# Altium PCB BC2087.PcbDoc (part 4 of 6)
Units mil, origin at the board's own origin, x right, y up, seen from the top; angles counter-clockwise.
Board outline 7401.57 x 1181.1 mil, 6 copper layers (Top Copper, Signal Layer 1, Signal Layer 2, Signal Layer 3, Signal Layer 4, Bottom Copper), stack 62.874 mil thick; 302 components, 237 nets, 1184 pads, 867 vias.
Unrouted connection lines stored in the file: 315.
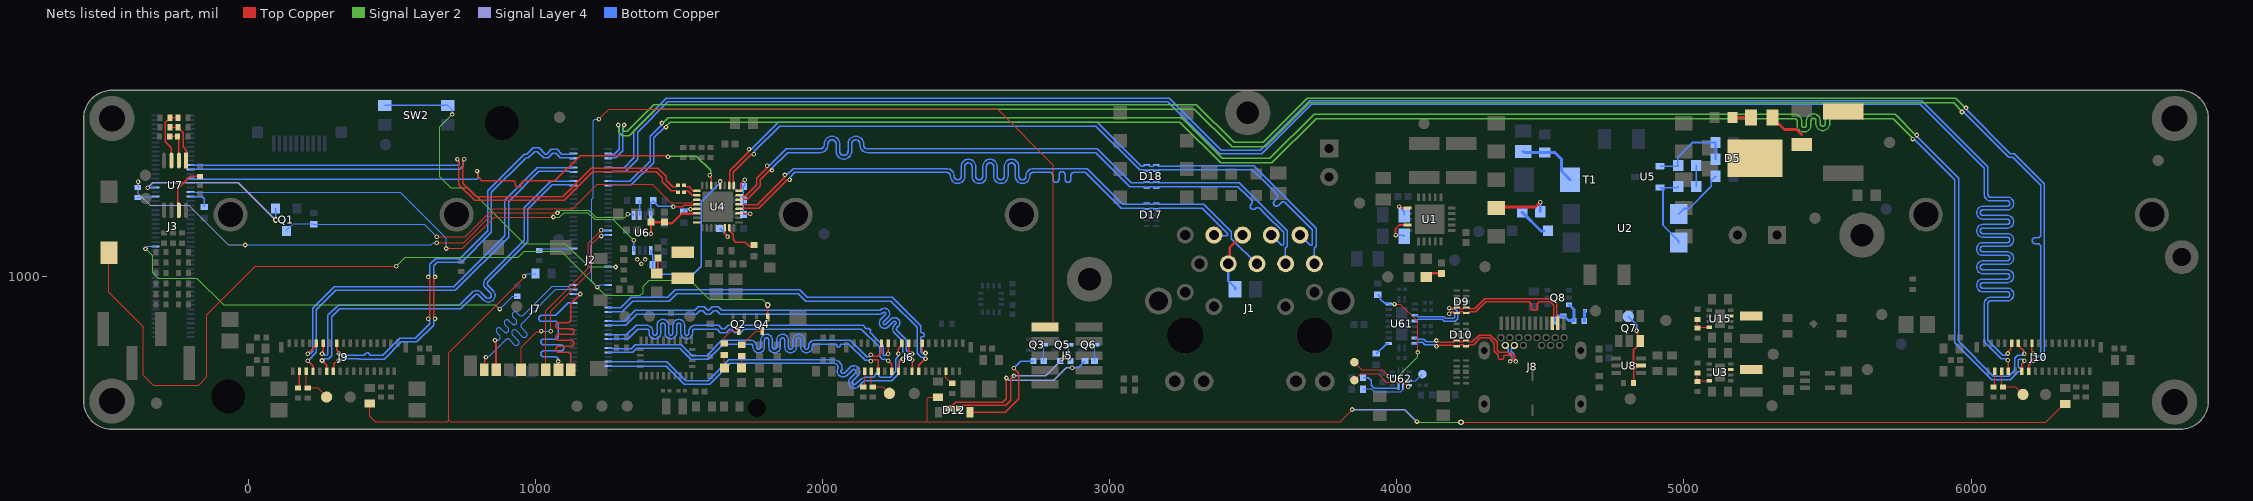
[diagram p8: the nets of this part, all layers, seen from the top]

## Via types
v1: diameter 20, hole 10, Top Copper to Bottom Copper, 273 vias
v2: diameter 16, hole 8, Top Copper to Bottom Copper, tented both sides, 243 vias
v3: diameter 15.98, hole 7.99, Top Copper to Bottom Copper, tented both sides, 201 vias
v4: diameter 18, hole 8, Top Copper to Bottom Copper, tented both sides, 70 vias
v5: diameter 16, hole 7.95, Top Copper to Bottom Copper, tented both sides, 36 vias
v6: diameter 20, hole 10, Top Copper to Bottom Copper, tented both sides, 26 vias
v7: diameter 16, hole 8, Top Copper to Bottom Copper, 17 vias
v8: diameter 19.68, hole 11.81, Top Copper to Bottom Copper, tented both sides, 1 vias

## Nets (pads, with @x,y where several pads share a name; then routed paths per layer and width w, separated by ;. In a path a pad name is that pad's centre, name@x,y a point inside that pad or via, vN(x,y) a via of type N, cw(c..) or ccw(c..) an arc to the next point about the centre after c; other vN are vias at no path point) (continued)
MD2_N: D17.5 D17.6 J1.6 U4.5 | length 2394.4
  Top Copper w5.12: U4.5@1708.96,1252.91 1719.55,1252.91 1721.03,1251.44 1771.68,1251.44 1867.87,1347.63 v3(1867.87,1355.2)
  Bottom Copper w5.12: v3(1867.87,1355.2) 1875.45,1355.2 1897.21,1376.96 2358.89,1376.96 2432.43,1376.96 cw(c2432.43,1351.77) 2457.62,1351.77 2457.62,1350.87 ccw(c2470.02,1350.87) 2470.02,1338.47 ccw(c2470.02,1350.87) 2482.42,1350.87 2482.42,1384.85 cw(c2507.61,1384.85) 2507.61,1410.04 cw(c2507.61,1384.85) 2532.8,1384.85 2532.8,1350.87 ccw(c2545.2,1350.87) 2545.2,1338.47 ccw(c2545.2,1350.87) 2557.61,1350.87 2557.61,1384.85 cw(c2582.8,1384.85) 2582.8,1410.04 cw(c2582.8,1384.85) 2607.99,1384.85 2607.99,1350.87 ccw(c2620.39,1350.87) 2620.39,1338.47 ccw(c2620.39,1350.87) 2632.79,1350.87 2632.79,1384.85 cw(c2657.98,1384.85) 2657.98,1410.04 cw(c2657.98,1384.85) 2683.18,1384.85 2683.18,1350.87 ccw(c2695.58,1350.87) 2695.58,1338.47 ccw(c2695.58,1350.87) 2707.98,1350.87 2707.98,1351.77 cw(c2733.17,1351.77) 2733.17,1376.96 2742.13,1376.96 2920.65,1376.96 3045.16,1252.46 3117.91,1252.46 3121.36,1255.91 D17.5@3128.54,1255.91 3135.73,1255.91 3139.18,1252.46 3150.78,1252.46 3154.23,1255.91 D17.6@3161.42,1255.91 3168.6,1255.91 3172.05,1252.46 3327.88,1252.46 3423.87,1156.47 3423.87,1133.42 3511.56,1045.73 J1.6@3512.6,1045.73
MD2_P: D17.4 D17.7 J1.3 U4.4 | length 2394.5
  Top Copper w5.12: U4.4@1708.96,1237.17 1719.55,1237.17 1721.03,1238.65 1776.98,1238.65 1876.92,1338.58 v3(1884.49,1338.58)
  Bottom Copper w5.12: v3(1884.49,1338.58) 1884.49,1346.16 1902.51,1364.17 2358.89,1364.17 2432.43,1364.17 cw(c2432.43,1351.77) 2444.83,1351.77 2444.83,1350.87 ccw(c2470.02,1350.87) 2470.02,1325.68 ccw(c2470.02,1350.87) 2495.21,1350.87 2495.21,1384.85 cw(c2507.61,1384.85) 2507.61,1397.25 cw(c2507.61,1384.85) 2520.01,1384.85 2520.01,1350.87 ccw(c2545.2,1350.87) 2545.2,1325.68 ccw(c2545.2,1350.87) 2570.4,1350.87 2570.4,1384.85 cw(c2582.8,1384.85) 2582.8,1397.25 cw(c2582.8,1384.85) 2595.2,1384.85 2595.2,1350.87 ccw(c2620.39,1350.87) 2620.39,1325.68 ccw(c2620.39,1350.87) 2645.58,1350.87 2645.58,1384.85 cw(c2657.98,1384.85) 2657.98,1397.25 cw(c2657.98,1384.85) 2670.39,1384.85 2670.39,1350.87 ccw(c2695.58,1350.87) 2695.58,1325.68 ccw(c2695.58,1350.87) 2720.77,1350.87 2720.77,1351.77 cw(c2733.17,1351.77) 2733.17,1364.17 2742.13,1364.17 2768.41,1364.17 2791.83,1364.17 cw(c2791.83,1353.74) 2802.26,1353.74 2802.26,1339.64 ccw(c2812.7,1339.64) 2812.7,1329.2 ccw(c2812.7,1339.64) 2823.13,1339.64 2823.13,1356.41 cw(c2833.56,1356.41) 2833.56,1366.85 cw(c2833.56,1356.41) 2844,1356.41 2844,1339.64 ccw(c2854.43,1339.64) 2854.43,1329.2 ccw(c2854.43,1339.64) 2864.86,1339.64 2864.86,1353.74 cw(c2875.3,1353.74) 2875.3,1364.17 2894.1,1364.17 2915.35,1364.17 3039.86,1239.67 3117.91,1239.67 3121.36,1236.22 D17.4@3128.54,1236.22 3135.73,1236.22 3139.18,1239.67 3150.78,1239.67 3154.23,1236.22 D17.7@3161.42,1236.22 3168.6,1236.22 3172.05,1239.67 3322.58,1239.67 3411.08,1151.17 3411.08,1146.93 3408.08,1143.93 3364.4,1143.93 J1.3@3362.6,1145.73
MD3_N: D18.2 D18.9 J1.8 U4.7 | length 2389.1
  Top Copper w5.12: U4.7@1708.96,1284.41 1719.55,1284.41 1721.03,1282.93 1732.17,1282.93 1770.14,1320.9 1770.14,1343.69 1806.52,1380.07 v3(1806.52,1387.64)
  Bottom Copper w5.12: v3(1806.52,1387.64) 1814.09,1387.64 1872.31,1445.86 1927.17,1445.86 1990.71,1445.86 ccw(c1990.71,1460.23) 2005.08,1460.23 2005.08,1463.14 cw(c2032.24,1463.14) 2032.24,1490.3 cw(c2032.24,1463.14) 2059.4,1463.14 2059.4,1437.55 ccw(c2073.77,1437.55) 2073.77,1423.18 ccw(c2073.77,1437.55) 2088.14,1437.55 2088.14,1463.14 cw(c2115.3,1463.14) 2115.3,1490.3 cw(c2115.3,1463.14) 2142.46,1463.14 2142.46,1460.23 ccw(c2156.83,1460.23) 2156.83,1445.86 2207.32,1445.86 2955.71,1445.86 3074.31,1327.26 3117.91,1327.26 3121.36,1330.71 D18.2@3128.54,1330.71 3135.73,1330.71 3139.18,1327.26 3150.78,1327.26 3154.23,1330.71 D18.9@3161.42,1330.71 3164.67,1330.71 3168.11,1327.26 3451.77,1327.26 3618.66,1160.37 3618.66,1107.4 3611.92,1100.65 3611.92,1046.41 J1.8@3612.6,1045.73
MD3_P: D18.1 D18.10 J1.7 U4.6 | length 2395.7
  Top Copper w5.12: U4.6@1708.96,1268.66 1719.55,1268.66 1721.03,1270.14 1737.47,1270.14 1782.93,1315.6 1782.93,1338.39 1815.56,1371.02 v3(1823.13,1371.02)
  Bottom Copper w5.12: v3(1823.13,1371.02) 1823.13,1378.6 1877.61,1433.07 1927.17,1433.07 1990.71,1433.07 ccw(c1990.71,1460.23) 2017.87,1460.23 2017.87,1463.14 cw(c2032.24,1463.14) 2032.24,1477.51 cw(c2032.24,1463.14) 2046.61,1463.14 2046.61,1437.55 ccw(c2073.77,1437.55) 2073.77,1410.38 ccw(c2073.77,1437.55) 2100.93,1437.55 2100.93,1463.14 cw(c2115.3,1463.14) 2115.3,1477.51 cw(c2115.3,1463.14) 2129.67,1463.14 2129.67,1460.23 ccw(c2156.83,1460.23) 2156.83,1433.07 2207.32,1433.07 2950.42,1433.07 3069.02,1314.47 3117.91,1314.47 3121.36,1311.02 D18.1@3128.54,1311.02 3135.73,1311.02 3139.18,1314.47 3150.78,1314.47 3154.23,1311.02 D18.10@3161.42,1311.02 3164.67,1311.02 3168.11,1314.47 3446.47,1314.47 3476.35,1284.59 3478.16,1282.78 3492.92,1268.03 cw(c3485.54,1260.65) 3492.92,1253.28 3492.7,1253.06 ccw(c3500.08,1245.68) 3492.7,1238.3 ccw(c3500.08,1245.68) 3507.45,1238.3 3507.67,1238.52 cw(c3515.05,1231.14) 3522.42,1238.52 3540.08,1220.86 3541.89,1219.05 3605.87,1155.07 3605.87,1112.69 3602.87,1109.7 3598.63,1109.7 J1.7@3562.6,1145.73 J1.7@3576.55,1145.73
MD4_N: D18.5 D18.6 J1.10 U4.10 | length 2453.9
  Top Copper w5.12: U4.10@1674.51,1318.86 1674.51,1329.45 1675.99,1330.93 1675.99,1369.15 1740.68,1433.84 1740.68,1441.41 v3(1743.52,1444.26)
  Bottom Copper w5.12: v3(1743.52,1444.26) 1745.6,1446.33 1753.18,1446.33 1845.22,1538.38 2956.74,1538.38 3108.81,1386.32 3117.91,1386.32 3121.36,1389.76 D18.5@3128.54,1389.76 3135.73,1389.76 3139.18,1386.32 3150.78,1386.32 3154.23,1389.76 D18.6@3161.42,1389.76 3164.67,1389.76 3168.11,1386.32 3242.07,1386.32 3242.56,1386.81 3501.36,1386.81 3718.66,1169.5 3718.66,1107.4 3711.92,1100.65 3711.92,1046.41 J1.10@3712.6,1045.73
MD4_P: D18.4 D18.7 J1.9 U4.9 | length 2449.8
  Top Copper w5.12: U4.9@1690.26,1318.86 1690.26,1329.45 1688.78,1330.93 1688.78,1363.85 1749.72,1424.79 1757.29,1424.79 v3(1760.14,1427.64)
  Bottom Copper w5.12: v3(1760.14,1427.64) 1762.22,1429.72 1762.22,1437.29 1850.52,1525.59 2951.45,1525.59 3103.51,1373.53 3117.91,1373.53 3121.36,1370.08 D18.4@3128.54,1370.08 3135.73,1370.08 3139.18,1373.53 3150.78,1373.53 3154.23,1370.08 D18.7@3161.42,1370.08 3164.67,1370.08 3168.11,1373.53 3247.37,1373.53 3247.86,1374.02 3496.06,1374.02 3565.45,1304.63 3567.26,1302.82 3582.02,1288.06 cw(c3574.64,1280.68) 3582.02,1273.31 3573.13,1264.42 ccw(c3580.51,1257.05) 3573.13,1249.67 ccw(c3580.51,1257.05) 3587.89,1249.67 3596.77,1258.55 cw(c3604.15,1251.18) 3611.53,1258.55 3640.61,1229.47 3642.42,1227.66 3705.87,1164.21 3705.87,1112.69 3702.87,1109.7 3698.63,1109.7 J1.9@3662.6,1145.73
MIPI_RX2_C_N: J2.95 J10.20 | length 6095.5
  Top Copper w5.12: J10.20@6200.93,671.88 6200.93,691.9 v2(6217.39,708.36)
  Signal Layer 2 w5.12: v5(1308,1529.07) 1305.4,1526.47 1305.4,1510.87 1308.4,1507.87 1318.9,1507.87 1411.31,1600.28 3301.29,1600.28 3432.94,1468.64 3534.64,1468.64 3687.94,1621.94 5946.39,1621.94 5979.62,1588.71 v2(5982.71,1588.71)
  Bottom Copper w5.12: J2.95@1252.95,1413.39 1253.94,1414.37 1266.14,1414.37 1266.64,1414.86 1279.71,1414.86 1303.98,1439.13 1303.98,1525.05 v5(1308,1529.07) ; v2(5982.71,1588.71) 5982.71,1583.61 6136.41,1429.9 6151.18,1429.9 6255.9,1325.19 6255.9,724.79 6240.32,709.21 6218.24,709.21 v2(6217.39,708.36)
MIPI_RX2_C_P: J2.97 J10.19 | length 6095.4
  Top Copper w5.12: J10.19@6212.45,768.34 6212.45,736.8 v2(6217.39,731.86)
  Signal Layer 2 w5.12: v5(1288,1529.07) 1289.76,1527.31 1289.76,1504.39 1301.92,1492.24 1325.38,1492.24 1417.78,1584.65 3294.81,1584.65 3426.46,1453 3541.12,1453 3694.41,1606.3 5939.92,1606.3 5968.57,1577.65 v2(5968.57,1574.57)
  Bottom Copper w5.12: J2.97@1252.95,1429.13 1253.94,1428.15 1266.14,1428.15 1266.64,1427.66 1274.41,1427.66 1291.19,1444.43 1291.19,1525.89 v5(1288,1529.07) ; v2(5968.57,1574.57) 5973.66,1574.57 6131.11,1417.11 6145.89,1417.11 6243.11,1319.89 6243.11,1170.28 6243.11,1146.85 cw(c6232.68,1146.85) 6232.68,1136.42 6223.78,1136.42 ccw(c6223.78,1125.98) 6213.35,1125.98 ccw(c6223.78,1125.98) 6223.78,1115.55 6232.68,1115.55 cw(c6232.68,1105.12) 6243.11,1105.12 6243.11,1084.47 6243.11,730.09 6235.02,722 6227.25,722 v2(6217.39,731.86)
MIPI_RX2_D0_N: J2.89 J10.26 | length 7120.3
  Top Copper w5.12: v2(6127.95,709.77) 6129.01,708.71 6129.01,672.94 J10.26@6130.07,671.88
  Bottom Copper w5.12: J2.89@1252.95,1366.14 1253.94,1367.13 1266.14,1367.13 1266.64,1367.62 1313.62,1367.62 1355.31,1409.31 1355.31,1504.63 1460.92,1610.24 3201.4,1610.24 3382.64,1429 3529,1429 3701.62,1601.62 5823.58,1601.62 6046.26,1378.93 6046.26,1296.26 6046.26,1287.31 ccw(c6068.5,1287.31) 6068.5,1265.07 6126.04,1265.07 cw(c6126.04,1255.62) 6126.04,1246.17 6041.34,1246.17 ccw(c6041.34,1223.93) 6041.34,1201.69 6126.04,1201.69 cw(c6126.04,1192.24) 6126.04,1182.79 6041.34,1182.79 ccw(c6041.34,1160.55) 6041.34,1138.31 6126.04,1138.31 cw(c6126.04,1128.87) 6126.04,1119.42 6041.34,1119.42 ccw(c6041.34,1097.18) 6041.34,1074.94 6126.04,1074.94 cw(c6126.04,1065.49) 6126.04,1056.04 6041.34,1056.04 ccw(c6041.34,1033.8) 6041.34,1011.56 6126.04,1011.56 cw(c6126.04,1002.11) 6126.04,992.67 6041.34,992.67 ccw(c6041.34,970.43) 6041.34,948.19 6126.04,948.19 cw(c6126.04,938.74) 6126.04,929.29 6068.5,929.29 ccw(c6068.5,907.05) 6046.26,907.05 6046.26,876.2 6046.26,773.84 6104.98,715.12 6118.57,715.12 6123.93,709.77 v2(6127.95,709.77)
MIPI_RX2_D0_P: J2.91 J10.25 | length 7122.3
  Top Copper w5.12: v2(6127.95,733.27) 6127.95,737.13 6138.52,747.7 6138.52,765.28 J10.25@6141.58,768.34
  Bottom Copper w5.12: J2.91@1252.95,1381.89 1253.94,1380.91 1266.14,1380.91 1266.64,1380.41 1308.32,1380.41 1342.52,1414.61 1342.52,1509.93 1455.62,1623.03 3206.7,1623.03 3387.93,1441.79 3523.7,1441.79 3696.32,1614.41 5828.87,1614.41 6059.06,1384.23 6059.06,1296.26 6059.06,1287.31 ccw(c6068.5,1287.31) 6068.5,1277.86 6126.04,1277.86 cw(c6126.04,1255.62) 6126.04,1233.38 6041.34,1233.38 ccw(c6041.34,1223.93) 6041.34,1214.48 6126.04,1214.48 cw(c6126.04,1192.24) 6126.04,1170 6041.34,1170 ccw(c6041.34,1160.55) 6041.34,1151.11 6126.04,1151.11 cw(c6126.04,1128.87) 6126.04,1106.63 6041.34,1106.63 ccw(c6041.34,1097.18) 6041.34,1087.73 6126.04,1087.73 cw(c6126.04,1065.49) 6126.04,1043.25 6041.34,1043.25 ccw(c6041.34,1033.8) 6041.34,1024.35 6126.04,1024.35 cw(c6126.04,1002.11) 6126.04,979.88 6041.34,979.88 ccw(c6041.34,970.43) 6041.34,960.98 6126.04,960.98 cw(c6126.04,938.74) 6126.04,916.5 6068.5,916.5 ccw(c6068.5,907.05) 6059.06,907.05 6059.06,876.2 6059.06,779.13 6110.28,727.91 6118.57,727.91 6123.93,733.27 v2(6127.95,733.27)
MIPI_RX2_D1_N: J2.83 J10.22 | length 6144.3
  Top Copper w5.12: J10.22@6177.31,671.88 6177.31,695.62 6186.02,704.33 v2(6186.02,708.36)
  Signal Layer 2 w5.12: v3(1454,1522) 1454,1524.73 1468.75,1539.48 3243.52,1539.48 3386,1397 3564.19,1397 3718.37,1551.18 5342.93,1551.18 5385.88,1551.18 cw(c5385.88,1542.72) 5394.34,1542.72 5394.34,1529.03 ccw(c5418.44,1529.03) 5418.44,1504.93 ccw(c5418.44,1529.03) 5442.55,1529.03 5442.55,1544.29 cw(c5451.01,1544.29) 5451.01,1552.76 cw(c5451.01,1544.29) 5459.48,1544.29 5459.48,1533.39 ccw(c5483.58,1533.39) 5483.58,1509.29 ccw(c5483.58,1533.39) 5507.68,1533.39 5507.68,1542.72 cw(c5516.14,1542.72) 5516.14,1551.18 5562.99,1551.18 5729.29,1551.18 5797.29,1483.18 v2(5797.29,1480.09)
  Bottom Copper w5.12: J2.83@1252.95,1318.9 1253.94,1319.88 1266.14,1319.88 1266.64,1320.38 1333.42,1320.38 1411.41,1398.36 1411.41,1454.86 1411.41,1484.16 1449.25,1522 v3(1454,1522) ; v2(5797.29,1480.09) 5802.39,1480.09 5943.9,1338.58 5943.9,770.29 6072.46,641.74 6137.19,641.74 6141.79,646.33 6164.78,669.33 cw(c6168.68,665.43) 6168.68,670.94 6170.9,670.94 ccw(c6170.9,676.45) 6170.9,681.97 ; 6170.87,681.97 cw(c6170.87,687.48) 6165.35,687.48 6165.35,699.35 6165.35,706.32 6165.35,710.72 6168.35,713.71 6177.72,713.71 6183.08,708.36 v2(6186.02,708.36)
MIPI_RX2_D1_P: J2.85 J10.23 | length 6140.3
  Top Copper w5.12: J10.23@6165.21,768.34 6165.21,761.45 6183.18,743.48 6183.18,734.71 v2(6186.02,731.86)
  Signal Layer 2 w5.12: v3(1439.87,1536.13) 1443.28,1536.13 1462.27,1555.12 3250,1555.12 3392.48,1412.64 3557.71,1412.64 3711.89,1566.82 5342.93,1566.82 5385.88,1566.82 cw(c5385.88,1542.72) 5409.98,1542.72 5409.98,1529.03 ccw(c5418.44,1529.03) 5418.44,1520.57 ccw(c5418.44,1529.03) 5426.91,1529.03 5426.91,1544.29 cw(c5451.01,1544.29) 5451.01,1568.39 cw(c5451.01,1544.29) 5475.11,1544.29 5475.11,1533.39 ccw(c5483.58,1533.39) 5483.58,1524.93 ccw(c5483.58,1533.39) 5492.04,1533.39 5492.04,1542.72 cw(c5516.14,1542.72) 5516.14,1566.82 5562.99,1566.82 5735.77,1566.82 5808.35,1494.24 v2(5811.44,1494.24)
  Bottom Copper w5.12: J2.85@1252.95,1334.65 1253.94,1333.66 1266.14,1333.66 1266.64,1333.17 1328.13,1333.17 1398.62,1403.66 1398.62,1489.46 1429.69,1520.52 1439.87,1530.7 v3(1439.87,1536.13) ; v2(5811.44,1494.24) 5811.44,1489.14 5956.69,1343.88 5956.69,775.59 6077.76,654.53 6131.89,654.53 6152.56,675.2 6152.56,694.05 6152.56,716.01 6162.92,726.38 6177.6,726.38 6183.08,731.86 v2(6186.02,731.86)
MIPI_RX3_C_N: J2.96 J9.20 | length 1402.2
  Top Copper w5.12: J9.20@295.42,671.88 297.32,673.78 297.32,697.81 300.94,701.43 303.58,701.43 310.93,708.78 v3(314.96,708.78) ; v3(649.61,854.33) 644.25,859.69 644.25,994.65 v3(649.61,1000)
  Bottom Copper w5.12: v3(314.96,708.78) 318.99,708.78 324.34,714.14 385.1,714.14 385.53,713.71 472.91,713.71 532.51,773.31 586.21,773.31 644.25,831.36 644.25,844.95 649.61,850.3 v3(649.61,854.33) ; v3(649.61,1000) 644.25,1005.35 644.25,1038.16 657.27,1051.18 741.72,1051.18 845.79,1155.25 845.79,1294.61 963.49,1412.31 966.05,1414.86 975,1414.86 996.43,1436.29 1006.43,1436.29 1027.85,1414.86 1043.15,1414.86 1059.77,1431.49 1069.77,1431.49 1086.4,1414.86 1098,1414.86 1118.01,1414.86 1118.5,1414.37 1130.71,1414.37 J2.96@1131.69,1413.39
MIPI_RX3_C_P: J2.98 J9.19 | length 1402.7
  Top Copper w5.12: J9.19@306.94,768.34 306.94,744.33 314.96,736.31 v3(314.96,732.28) ; v3(626.11,854.33) 631.46,859.69 631.46,994.65 v3(626.11,1000)
  Bottom Copper w5.12: v3(314.96,732.28) 318.99,732.28 324.34,726.93 391.29,726.93 391.71,726.5 400.59,726.5 403.15,726.5 407.05,730.4 407.05,732.18 410.95,736.08 416.14,736.08 420.04,732.18 420.04,730.4 423.94,726.5 437.41,726.5 467.61,726.5 527.21,786.1 580.91,786.1 631.46,836.65 631.46,844.95 626.11,850.3 v3(626.11,854.33) ; v3(626.11,1000) 631.46,1005.35 631.46,1043.46 651.97,1063.97 736.42,1063.97 833,1160.55 833,1299.91 960.75,1427.66 963.4,1427.66 969.7,1427.66 991.13,1449.08 1011.72,1449.08 1033.15,1427.66 1037.85,1427.66 1054.48,1444.28 1075.07,1444.28 1091.69,1427.66 1098,1427.66 1118.01,1427.66 1118.5,1428.15 1130.71,1428.15 J2.98@1131.69,1429.13
MIPI_RX3_D0_N: J2.90 J9.26 | length 1403.7
  Top Copper w5.12: v3(205.71,708.36) 224.55,689.51 J9.26@224.55,671.88
  Bottom Copper w5.12: v3(205.71,708.36) 207.47,708.36 236.39,737.28 236.39,886 303.15,952.76 720.47,952.76 905.79,1138.07 905.79,1262.11 1011.3,1367.62 1118.01,1367.62 1118.5,1367.13 1130.71,1367.13 J2.90@1131.69,1366.14
MIPI_RX3_D0_P: J2.92 J9.25 | length 1403.8
  Top Copper w5.12: v3(205.71,731.86) 206.48,731.86 236.07,761.45 J9.25@236.07,768.34
  Bottom Copper w5.12: v3(205.71,731.86) 207.49,733.64 215.85,733.64 223.6,741.4 223.6,891.3 297.85,965.55 715.17,965.55 893,1143.37 893,1267.41 1006,1380.41 1118.01,1380.41 1118.5,1380.91 J2.92@1130.71,1380.91
MIPI_RX3_D1_N: J2.84 J9.22 | length 1407.5
  Top Copper w5.12: v3(255.91,708.78) 271.8,692.89 J9.22@271.8,671.88
  Bottom Copper w5.12: v3(255.91,708.78) 259.93,708.78 265.29,714.14 278.88,714.14 289.37,724.63 289.37,861.05 317.1,888.78 733.05,888.78 739.18,888.78 787.01,936.61 cw(c794.38,929.24) 801.76,936.61 819.19,919.18 ccw(c835.61,935.6) 852.04,919.18 ccw(c835.61,935.6) 852.04,952.02 834.6,969.46 cw(c841.98,976.83) 834.6,984.21 840.94,990.54 972.79,1122.4 972.79,1236.14 1057.03,1320.38 1119.98,1320.38 1120.47,1319.88 1130.71,1319.88 J2.84@1131.69,1318.9
MIPI_RX3_D1_P: J2.86 J9.23 | length 1401.6
  Top Copper w5.12: v3(255.91,732.28) 258.75,735.13 258.75,741.69 259.69,742.63 J9.23@259.69,768.34
  Bottom Copper w5.12: v3(255.91,732.28) 259.93,732.28 265.29,726.93 273.58,726.93 276.58,729.93 276.58,866.35 311.81,901.57 720.26,901.57 733.88,901.57 777.96,945.66 cw(c794.38,929.24) 810.81,945.66 828.24,928.22 ccw(c835.61,935.6) 842.99,928.22 ccw(c835.61,935.6) 842.99,942.98 825.59,960.38 cw(c841.98,976.83) 825.56,993.25 831.89,999.59 960,1127.69 960,1241.44 1051.73,1333.17 1118.01,1333.17 1118.5,1333.66 1130.71,1333.66 J2.86@1131.69,1334.65
MIPI_RX4_C_N: J2.3 J6.20 | length 1332
  Top Copper w5.12: J6.20@2263.92,671.88 2263.92,698.6 v3(2279.53,714.2)
  Bottom Copper w5.12: J2.3@1252.95,688.98 1455.02,688.98 1517.75,626.25 1605.99,626.25 1609.74,630 1678.56,698.82 2022.43,698.82 2040.87,698.82 cw(c2037.28,681.91) 2054.46,683.86 ccw(c2070.77,671.83) 2056.44,657.5 ccw(c2070.77,671.83) 2085.11,657.5 2103.05,675.44 cw(c2108.31,670.13) 2113.6,675.42 cw(c2108.31,670.13) 2113.6,664.84 2095.71,646.95 ; 2095.68,646.92 ccw(c2110.02,632.59) 2095.68,618.26 ccw(c2110.02,632.59) 2124.35,618.26 2139.35,633.25 cw(c2151.55,621) 2151.59,638.29 2157.82,638.29 2240.05,638.29 2267,665.24 2267,708 2273.2,714.2 v3(2279.53,714.2)
MIPI_RX4_C_P: J2.5 J6.19 | length 1334
  Top Copper w5.12: v3(2263.78,731.86) 2263.78,749.78 2275.44,761.45 J6.19@2275.44,768.34
  Bottom Copper w5.12: J2.5@1252.95,704.72 1457.36,704.72 1523.04,639.04 1600.7,639.04 1673.27,711.61 2035.22,711.61 2042.07,711.61 2042.68,711.5 cw(c2037.28,681.91) 2067.36,681.65 2067.34,678.98 2065.46,677.1 ccw(c2070.77,671.83) 2065.48,666.55 ccw(c2070.77,671.83) 2076.06,666.55 2093.95,684.44 cw(c2108.31,670.13) 2122.64,684.46 cw(c2108.31,670.13) 2122.64,655.79 2104.7,637.85 ccw(c2110.02,632.59) 2104.73,627.3 ccw(c2110.02,632.59) 2115.31,627.3 2130.31,642.31 cw(c2151.55,621) 2151.55,651.08 ; 2151.58,651.08 2159.64,651.08 2173.23,651.08 2175.79,651.08 ccw(c2175.79,657.58) 2182.28,657.58 2182.28,658.22 cw(c2188.78,658.22) 2188.78,664.72 cw(c2188.78,658.22) 2195.28,658.22 2195.28,657.58 ccw(c2201.77,657.58) 2201.77,651.08 2218.5,651.08 2234.75,651.08 2254.21,670.54 2254.21,713.3 2263.78,722.87 v3(2263.78,731.86)
MIPI_RX4_D0_N: J2.9 J6.26 | length 1338.8
  Top Copper w5.12: v3(2167.32,705.83) 2170.26,705.83 2175.62,711.19 2190.06,711.19 2193.06,708.19 J6.26@2193.06,671.88
  Bottom Copper w5.12: J2.9@1252.95,736.22 1253.94,737.2 1266.14,737.2 1266.64,737.7 1337.89,737.7 1351.57,751.38 1502.23,751.38 1540.61,713 1601.09,713 1654.33,766.25 1712.45,766.25 1749.15,766.25 cw(c1749.15,758.77) 1756.63,758.77 1756.63,755.99 ccw(c1776.9,755.99) 1797.17,755.99 1797.17,780.12 cw(c1804.65,780.12) 1812.13,780.12 1812.13,755.99 ccw(c1832.4,755.99) 1852.68,755.99 1852.68,780.12 cw(c1860.16,780.12) 1867.64,780.12 1867.64,755.99 ccw(c1887.91,755.99) 1908.18,755.99 1908.18,780.12 cw(c1915.66,780.12) 1923.14,780.12 1923.14,755.99 ccw(c1943.41,755.99) 1963.68,755.99 1963.68,758.77 cw(c1971.16,758.77) 1971.16,766.25 1994.12,766.25 2030.51,766.25 2044.1,766.25 cw(c2044.1,760.73) 2049.61,760.73 ccw(c2055.12,760.73) 2060.63,760.73 cw(c2066.14,760.73) 2066.14,766.25 2086.61,766.25 2091.3,766.25 2148.54,709 2164.15,709 v3(2167.32,705.83)
MIPI_RX4_D0_P: J2.11 J6.25 | length 1338.7
  Top Copper w5.12: v3(2167.32,729.33) 2170.26,729.33 2175.62,723.98 2191.9,723.98 2204.58,736.65 J6.25@2204.58,768.34
  Bottom Copper w5.12: J2.11@1252.95,751.97 1253.94,750.98 1266.14,750.98 1266.64,750.49 1332.59,750.49 1346.27,764.17 1507.53,764.17 1545.91,725.79 1595.79,725.79 1649.04,779.04 1712.45,779.04 1749.15,779.04 cw(c1749.15,758.77) 1769.42,758.77 1769.42,755.99 ccw(c1776.9,755.99) 1784.38,755.99 1784.38,780.12 cw(c1804.65,780.12) 1824.92,780.12 1824.92,755.99 ccw(c1832.4,755.99) 1839.89,755.99 1839.89,780.12 cw(c1860.16,780.12) 1880.43,780.12 1880.43,755.99 ccw(c1887.91,755.99) 1895.39,755.99 1895.39,780.12 cw(c1915.66,780.12) 1935.93,780.12 1935.93,755.99 ccw(c1943.41,755.99) 1950.89,755.99 1950.89,758.77 cw(c1971.16,758.77) 1971.16,779.04 1994.12,779.04 2096.59,779.04 2153.63,722 2159.99,722 v3(2167.32,729.33)
MIPI_RX4_D1_N: J2.15 J6.22 | length 1334.9
  Top Copper w5.12: v3(2228.35,708.36) 2240.3,696.4 J6.22@2240.3,671.88
  Bottom Copper w5.12: J2.15@1252.95,783.46 1253.94,784.45 1266.14,784.45 1266.64,784.94 1321.73,784.94 1355.12,818.33 1360.65,818.33 1387.61,818.33 cw(c1387.61,810.85) 1395.09,810.85 1395.09,804.15 ccw(c1415.36,804.15) 1435.63,804.15 1435.63,831.86 cw(c1443.11,831.86) 1450.59,831.86 1450.59,804.15 ccw(c1470.86,804.15) 1491.13,804.15 1491.13,831.86 cw(c1498.61,831.86) 1506.09,831.86 1506.09,804.15 ccw(c1526.36,804.15) 1546.63,804.15 1546.63,810.85 cw(c1554.11,810.85) 1554.11,818.33 1563.07,818.33 1621.44,818.33 1631.8,818.33 1643.8,806.33 1664.4,806.33 1676.4,818.33 1681.1,818.33 1693.1,806.33 1713.69,806.33 1725.69,818.33 1732,818.33 2135.03,818.33 2197.84,755.53 2197.84,723.25 2207.38,713.71 2220.05,713.71 2225.41,708.36 v3(2228.35,708.36)
MIPI_RX4_D1_P: J2.17 J6.23 | length 1338.4
  Top Copper w5.12: J6.23@2228.2,768.34 2228.27,768.26 v3(2228.35,731.86) v3(2228.35,731.86)
  Bottom Copper w5.12: J2.17@1252.95,799.21 1253.94,798.23 1266.14,798.23 1266.64,797.73 1316.43,797.73 1349.83,831.12 1360.65,831.12 1387.61,831.12 cw(c1387.61,810.85) 1407.88,810.85 1407.88,804.15 ccw(c1415.36,804.15) 1422.84,804.15 1422.84,831.86 cw(c1443.11,831.86) 1463.38,831.86 1463.38,804.15 ccw(c1470.86,804.15) 1478.34,804.15 1478.34,831.86 cw(c1498.61,831.86) 1518.88,831.86 1518.88,804.15 ccw(c1526.36,804.15) 1533.84,804.15 1533.84,810.85 cw(c1554.11,810.85) 1554.11,831.12 1563.07,831.12 1621.44,831.12 1637.1,831.12 1649.1,819.12 1659.1,819.12 1671.1,831.12 1686.4,831.12 1698.4,819.12 1708.4,819.12 1720.4,831.12 1732,831.12 2140.33,831.12 2149.44,822.02 2151.25,820.21 ccw(c2154.87,823.83) 2158.49,820.21 cw(c2160.05,818.65) 2161.61,820.21 2166.28,815.53 cw(c2164.72,813.97) 2166.28,812.41 ccw(c2169.9,808.79) 2166.28,805.17 2172.01,799.45 2173.81,797.64 2210.63,760.83 2210.63,728.55 2212.68,726.5 2220.05,726.5 2225.41,731.86 v3(2228.35,731.86)
MIPI_RX5_D0_N: J2.21 J6.16 | length 1333.7
  Top Copper w5.12: J6.16@2311.17,671.88 v3(2311.17,711.52)
  Bottom Copper w5.12: J2.21@1252.95,830.71 1253.94,831.69 1266.14,831.69 1266.63,832.18 1278.2,832.18 1314.2,832.18 1352.59,870.57 1548,870.57 1559.6,870.57 1571.6,882.57 1581.6,882.57 1593.6,870.57 1608.9,870.57 1620.9,882.57 1630.9,882.57 1642.9,870.57 1686.4,870.57 2144.2,870.57 2197.84,870.57 ccw(c2197.84,888.88) 2210.78,875.93 cw(c2214.68,872.04) 2218.58,875.93 cw(c2214.68,872.04) 2218.58,868.14 2202.9,852.47 ccw(c2215.84,839.52) 2228.79,826.58 2246.28,844.08 cw(c2250.18,840.18) 2254.07,844.08 cw(c2250.18,840.18) 2254.07,836.28 ; 2254.05,836.26 2249.05,831.26 ccw(c2261.99,818.32) 2249.05,805.37 2272.22,782.2 2278.33,776.09 2278.33,739.24 2304.29,713.28 2311,713.28 2311,712 2311.17,711.83 v3(2311.17,711.52)
MIPI_RX5_D0_P: J2.23 J6.17 | length 1335.6
  Top Copper w5.12: J6.17@2299.06,768.34 2299.06,743.44 v3(2311,731.5)
  Bottom Copper w5.12: J2.23@1252.95,846.46 1253.94,845.47 1266.14,845.47 1266.64,844.97 1283.5,844.97 1308.9,844.97 1347.3,883.36 1548,883.36 1554.31,883.36 1566.31,895.36 1586.9,895.36 1598.9,883.36 1603.6,883.36 1615.6,895.36 1636.2,895.36 1648.2,883.36 1686.4,883.36 2197.84,883.36 ccw(c2197.84,888.88) 2201.74,884.98 cw(c2214.68,872.04) 2227.62,884.98 cw(c2214.68,872.04) 2227.62,859.1 2211.97,843.44 ccw(c2215.84,839.52) 2211.93,835.64 ; 2211.96,835.61 ccw(c2215.84,839.52) 2219.74,835.63 2237.23,853.12 cw(c2250.18,840.18) 2263.12,853.12 cw(c2250.18,840.18) 2264.99,829.43 2264.99,829.11 2258.09,822.21 ccw(c2261.99,818.32) 2258.09,814.42 2281.27,791.25 2291.12,781.39 2291.12,744.54 2308.33,727.33 2311,730 v3(2311,731.5)
MIPI_RX5_D1_N: J2.27 J6.14 | length 1332.2
  Top Copper w5.12: J6.14@2334.79,671.88 2334.79,692.83 2357.05,715.1 v3(2358,715.1)
  Bottom Copper w5.12: J2.27@1252.95,877.95 1253.94,878.94 1266.14,878.94 1266.71,879.51 1302.34,879.51 1338.68,915.85 1465.85,915.85 1491.96,941.96 1914.96,941.96 1941.06,915.85 2237.71,915.85 2328.53,825.03 2328.53,734.01 2342.73,719.81 2353.29,719.81 v3(2358,715.1)
MIPI_RX5_D1_P: J2.29 J6.13 | length 1335.7
  Top Copper w5.12: J6.13@2346.31,768.34 2346.31,738.34 2349.57,735.08 v3(2358,735.08)
  Bottom Copper w5.12: J2.29@1252.95,893.7 1253.94,892.72 1266.14,892.72 1266.56,892.3 1297.04,892.3 1333.39,928.64 1460.55,928.64 1486.66,954.75 1920.25,954.75 1946.36,928.64 2243.01,928.64 2341.32,830.33 2341.32,813.98 2341.32,811.42 ccw(c2347.81,811.42) 2347.81,804.92 2348.03,804.92 cw(c2348.03,798.42) 2354.52,798.42 cw(c2348.03,798.42) 2348.03,791.93 2347.81,791.93 ccw(c2347.81,785.43) 2341.32,785.43 2341.32,771.65 ; 2341.32,771.17 2341.32,739.31 2348.03,732.6 2355.52,732.6 v3(2358,735.08)
MODULE_nRST: B1.2 J2.39 J5.1 Q4.1 | length 6078.9
  Top Copper w4.02: B1.2@-487,1084 -487,945.99 -367,825.99 -367,657.87 -331.78,622.64 -174.36,622.64 -145.18,651.82 -145.18,867.82 24,1037 v3(514,1037) ; v3(1220.41,1548.98) 1254.74,1583.31 2609.6,1583.31 2803.15,1389.76 2803.15,838.35 2790.2,825.39 J5.1@2774.61,825.39
  Top Copper w5: Q4.1@1808.68,859.02 v6(1808.68,902.07)
  Signal Layer 2 w4.02: v3(514,1037) 546,1069 940,1069 960.43,1089.43 1089.7,1089.43 v3(1214.57,964.57) 1243.13,936 1365,936 1374,945 1374,967 1395,988 1538.81,988 1604.81,922 1788.75,922 v6(1808.68,902.07)
  Bottom Copper w4.02: v3(1220.41,1548.98) 1205.17,1548.98 1200.07,1543.88 1200.07,1275.07 1194.74,1269.74 1194.74,984.39 v3(1214.57,964.57) 1217.81,964.57 1225.68,972.44 J2.39@1252.95,972.44
NetC4_1: C4.1 D4.1 R4.1 | length 227.5
  Bottom Copper w9.84: C4.1@4440.52,1437.01 4444.45,1433.07 4549.77,1433.07 4573.12,1409.72 4573.12,1368.66 D4.1@4603.19,1338.58
NetC5_1: C5.1 R5.1 | length 65
  Top Copper w9.84: C5.1@5169.29,1555.12 R5.1@5234.25,1555.12
NetC6_2: C6.2 D5.1 L1.1 R5.2 | length 128.9
  Top Copper w9.84: R5.2@5309.06,1555.12 5309.06,1548.23 5324.8,1532.48 5331.69,1532.48 5350.39,1513.78 5391.73,1513.78 5409.45,1496.06
NetC23_1: C23.1 U2.2 U5.2 | length 282.5
  Bottom Copper w5.91: U5.2@4917.16,1311.02 U5.2@4919.15,1311.02 ; C23.1@4980.15,1314.96 4976.21,1311.02 U5.2@4919.15,1311.02 ; U2.2@4982.25,1119.29 4982.25,1124.41 4927.03,1179.63 4927.03,1303.15 U5.2@4919.15,1311.02
NetC23_2: C23.2 R17.2 | length 72.8
  Bottom Copper w5.91: C23.2@5043.14,1314.96 R17.2@5043.14,1387.8
NetC24_2: C24.2 R18.1 | length 58.7
  Top Copper w7.87: R18.1@4102.75,1000 4115.22,1012.48 C24.2@4156.26,1012.48
NetC29_1: C29.1 Q8.3 R76.1 R78.2 | length 155.9
  Bottom Copper w10: C29.1@4546.46,840 4547.14,840.68 4547.14,853.91 4557.4,864.17 R78.2@4579.56,864.17 ; R78.2@4581.53,864.17 4585.39,860.32 4597.44,848.26 4615.88,848.26 R76.1@4617.28,846.86 ; Q8.3@4599.4,902.41 4601.37,902.41 4617.28,886.5 R76.1@4617.28,848.83
NetC30_1: C30.1 R76.2 | length 36
  Bottom Copper w10: R76.2@4652.72,846.86 4653.92,848.06 4653.92,880.69 C30.1@4655.11,881.89
NetC50_2: C50.2 J1.4 J1.5 | length 220.7
  Top Copper w7.87: J1.4@3412.6,1045.73 3417.79,1050.92 3417.79,1102.43 3461.09,1145.73 J1.5@3462.6,1145.73
  Bottom Copper w7.87: J1.4@3412.6,1045.73 3412.6,987.01 3437.01,962.6 C50.2@3437.01,956.69
NetD2_2: D2.2 R3.1 | length 104
  Bottom Copper w9.84: R3.1@4435.6,1224.41 4436.58,1225.39 4501.54,1160.43 D2.2@4512.3,1160.43
NetD12_2: D12.2 R65.2 | length 590.3
  Top Copper w5: D12.2@2440.28,541.48 2442.48,541.48 2464,563 2626.54,563 2640,576.46
  Top Copper w5.17: 2640,576.46 v3(2640,648)
  Signal Layer 4 w5.17: v3(2640,648) 2648.24,639.76 2804.41,639.76 2848.51,683.87 v3(2868.91,683.87)
  Bottom Copper w5.17: v3(2868.91,683.87) 2889.57,683.87 2912.4,706.69 R65.2@2913.39,706.69
NetD12_3: D12.3 R64.2 | length 499.8
  Top Copper w5: D12.3@2475.72,541.48 2476.7,541.48 2485.03,549.81 2485.03,550.03 2488,553 2637.5,553 2655,570.5
  Top Copper w5.17: 2655,570.5 2655,644 v3(2666,655)
  Signal Layer 4 w5.17: v3(2666,655) 2776.06,655 v3(2840.52,719.46)
  Bottom Copper w5.17: R64.2@2827.76,706.69 v3(2840.52,719.46)
NetD12_4: D12.4 R63.2 | length 382.9
  Top Copper w5: D12.4@2513.12,528.68 2636.47,528.68 2683,575.22
  Top Copper w5.17: v3(2665,682) 2683,664 2683,575.22
  Bottom Copper w5.17: v3(2665,682) 2689.69,706.69 R63.2@2734.25,706.69
NetJ2_47: J2.47 SW2.2 SW2.4 | length 1261
  Signal Layer 2 w4: v3(709.65,1565.94) 666.34,1522.64 666.34,1349.41 704.72,1311.02 765.75,1311.02 960.5,1116.28 1103.72,1116.28 1185,1035 1277.87,1035 v3(1278.31,1034.56)
  Bottom Copper w4: SW2.2@694.24,1597.46 709.65,1582.06 v3(709.65,1565.94) ; J2.47@1252.95,1035.43 1253.39,1035 1277.87,1035 v3(1278.31,1034.56)
  Bottom Copper w5: SW2.4@473.76,1597.46 SW2.2@694.24,1597.46
NetJ2_56: J2.56 R82.2 | length 121.9
  Bottom Copper w4: R82.2@1012.28,1092.43 1018.27,1098.43 J2.56@1131.69,1098.43
NetJ3_42: J3.42 R83.2 | length 1472.3
  Signal Layer 2 w4: v2(-359,1098) -334,1073 -334,1016 -314,996 -180,996 -87,903 860,903 v2(875,888)
  Bottom Copper w4: v2(-359,1098) -350.7,1106.3 J3.42@-324.02,1106.3 ; v2(875,888) 919.57,932.57 R83.2@936,932.57
NetJ3_64: J3.64 R27.1 | length 63.3
  Bottom Copper w4: R27.1@-386,1276.28 -382.76,1279.53 J3.64@-324.02,1279.53
NetJ6_6: J6.6 R61.1 | length 52.3
  Top Copper w4: J6.6@2429.28,671.88 2429.28,649.47 2449.03,629.72 R61.1@2451,629.72
NetJ6_28: J6.28 R54.1 TP32.1 | length 124.4
  Top Copper w4: R54.1@2173.99,616.89 2209.88,616.89 TP32.1@2232.28,594.49
  Top Copper w4.02: J6.28@2169.44,671.88 2169.44,621.45 R54.1@2173.99,616.89
NetJ6_30: J6.30 R60.2 | length 56.8
  Top Copper w4: R60.2@2141.46,616.89 2145.81,621.25 J6.30@2145.81,671.88
NetJ9_28: J9.28 R136.1 TP18.1 | length 139.5
  Top Copper w4: R136.1@206.21,613.19 240.3,613.19 TP18.1@271.8,581.69
  Top Copper w4.02: J9.28@200.93,671.88 200.93,618.46 R136.1@206.21,613.19
NetJ9_30: J9.30 R41.1 | length 60.6
  Top Copper w5: R41.1@172.6,613.19 177.31,617.9 J9.30@177.31,671.88
NetJ10_28: J10.28 R135.1 TP14.1 | length 137.6
  Top Copper w4: J10.28@6106.44,671.88 6106.44,621.87 R135.1@6111.19,617.13 6154.53,617.13 TP14.1@6181.1,590.55
NetJ10_30: J10.30 R71.1 | length 56.4
  Top Copper w4: R71.1@6078.82,617.13 6082.82,621.12 J10.30@6082.82,671.88
NetL3_1: L3.1 U15.7
NetL4_1: L4.1 U3.7
NetQ2_3: Q2.3 R53.1 | length 79.4
  Top Copper w4: R53.1@1657.48,767.72 1657.48,788.11 1680.35,810.98 Q2.3@1707,810.98
NetQ3_3: Q3.3 R63.1 | length 57.5
  Bottom Copper w4.02: R63.1@2769.68,706.69 2770.67,707.68 Q3.3@2770.67,763.78
NetQ4_3: Q4.3 R56.1 | length 90.9
  Top Copper w4: R56.1@1717.63,763.78 1726.45,772.61 1728.61,772.61 1766.98,810.98 Q4.3@1789,810.98
NetQ5_3: Q5.3 R64.1 | length 61.4
  Bottom Copper w4.02: Q5.3@2859.65,763.78 2856.24,760.38 2856.24,740.07 2863.19,733.13 R64.1@2863.19,706.69
NetQ6_3: Q6.3 R65.1 | length 58.5
  Bottom Copper w4.02: R65.1@2946.85,706.69 2946.85,760.43 Q6.3@2950.2,763.78
NetQ7_3: Q7.3 R69.1 TP17.1 U8.5 | length 281.3
  Top Copper w6: R69.1@4824.8,630.39 4824.8,675.2 U8.5@4840.55,690.94 ; v5(4835.05,812.65) 4835.05,809.95 4837.65,807.35 4837.65,787.35 Q7.3@4847.44,777.56 4847.44,769.49 4824.65,746.69 4824.65,706.85 U8.5@4840.55,690.94 ; U8.5@4850.39,690.94 U8.5@4840.55,690.94
  Bottom Copper w6: TP17.1@4806.1,862.2 4835.05,833.26 v5(4835.05,812.65)
NetR3_2: R3.2 T1.2 | length 192.4
  Top Copper w9.84: T1.2@4347.01,1242.13 4350.95,1242.13 4352.92,1244.09 4483.14,1244.09 4498.89,1259.84 v3(4499.57,1259.84)
  Bottom Copper w9.84: R3.2@4499.57,1227.36 v3(4499.57,1259.84)
NetR14_1: R14.1 R15.2 R17.1 U5.1 | length 304.8
  Bottom Copper w5.91: U5.1@4917.16,1385.83 4978.18,1385.83 R17.1@4980.15,1387.8 4978.97,1388.98 4978.97,1416.34 5031.13,1468.5 R14.1@5110.24,1468.5 R15.2@5110.24,1409.45
NetR24_1: R24.1 U2.1 | length 193.8
  Bottom Copper w5.91: U2.1@4982.25,1219.29 5001,1238.04 5017.57,1238.04 5095.47,1315.94 5095.47,1335.63 R24.1@5110.24,1350.39
NetR33_1: R33.1 R34.2 U3.4 | length 71.3
  Top Copper w4: R34.2@5047.24,665.26 R33.1@5047.24,636.13 5049.21,638.1 U3.4@5088.58,638.1
NetR38_1: R38.1 R39.1 R75.1 R77.1 | length 6802.3
  Top Copper w4: R77.1@422.01,558.57 422.01,514.99 442.07,494.93 691.4,494.93 696.85,500.38 ; v3(959.72,1002.07) 959.72,999.09 696.85,736.22 696.85,500.38 ; R38.1@2402,580.93 2401.64,580.57 2369.93,580.57 2364.32,574.96 2364.32,494.93 ; v7(3845,538) 3801.93,494.93 2364.32,494.93 ; v6(4223.14,493.93) 4223.14,493 6259.6,493 6324.51,557.91 R75.1@6328.45,557.91 ; 696.85,500.38 702.3,494.93 2364.32,494.93
  Signal Layer 2 w4: v2(4070,496) 4072.07,493.93 v6(4223.14,493.93)
  Signal Layer 4 w5: v7(3845,538) 4028,538 v2(4070,496)
  Bottom Copper w4: v3(959.72,1002.07) 959.72,1002.91 968.62,1011.81 R39.1@1000,1011.81
NetR48_2: R48.2 U4.31 | length 130.8
  Top Copper w5: U4.31@1674.51,1171.22 1674.51,1162.02 1688.22,1148.31 1688.22,1130.96 1697.89,1121.29 1729.74,1121.29 1744.71,1106.32 1753.75,1106.32 1758.65,1111.22 R48.2@1760.83,1111.22
NetR50_1: R50.1 U6.6 | length 53.8
  Bottom Copper w5: R50.1@1357.87,1266.18 1362.09,1261.97 U6.6@1362.09,1214.17
NetR51_1: R51.1 R52.2 U15.4 | length 72.2
  Top Copper w4: R52.2@5047.24,851.97 R51.1@5047.24,822.16 5049.89,824.8 U15.4@5088.58,824.8
NetR128_1: R128.1 R132.2 U7.1 | length 155.6
  Top Copper w5: R132.2@-273.84,1521.62 R128.1@-246.28,1521.62 -246.28,1519.66 -228.35,1501.72 -228.35,1452.76 -217.52,1441.93 U7.1@-217.52,1405.51
NetR129_1: R129.1 R133.2 U7.2 | length 112.9
  Top Copper w5: R133.2@-274.61,1489.17 R129.1@-247.05,1489.17 -243.11,1485.24 U7.2@-243.11,1405.51
NetR130_1: R130.1 R134.2 U7.3 | length 193.1
  Top Copper w5: U7.3@-268.7,1405.51 -268.7,1449.35 -289.96,1470.61 -289.96,1538 -281.95,1546.02 -279.98,1546.02 -273.62,1552.38 R134.2@-273.62,1554.35 R130.1@-246.06,1554.35
NetR131_2: R131.2 U7.7 | length 170.8
  Top Copper w5: U7.7@-243.11,1232.28 -244.79,1233.96 -244.79,1259 -246.06,1260.27 -246.06,1307.44 -203.35,1350.16 R131.2@-169.29,1350.16
NetR185_1: R185.1 U61.2 | length 57.9
  Bottom Copper w5: R185.1@3928.58,733.36 3930.55,733.36 3962.78,765.58 3965.2,768.01 U61.2@3972.09,768.01
NetR186_1: R186.1 TP41.1 U61.9 U62.11 | length 588.3
  Top Copper w4: TP41.1@3852,703 3877.69,677.31 3948.51,677.31 v3(3972.18,653.64) ; v3(3991.7,905.48) 4012.46,905.48 4072.84,845.1 v3(4072.84,736.91)
  Signal Layer 2 w4: v3(3972.18,653.64) 4004.39,653.64 4072.84,722.09 v3(4072.84,736.91)
  Bottom Copper w4: U61.9@3972.09,905.8 3972.25,905.64 3991.54,905.64 v3(3991.7,905.48) ; v3(3972.18,653.64) 3972.27,653.74 3986.12,653.74 U62.11@3986.22,653.83
  Bottom Copper w5: R186.1@3933.54,937.89 3934.55,937.89 3942.87,929.57 3942.87,922.99 3957.69,908.17 3969.72,908.17 U61.9@3972.09,905.8
NetR213_1: R213.1 U62.7 | length 160.3
  Bottom Copper w4.02: R213.1@3882.34,608.16 3884.43,610.25 3910.76,610.25 3920.43,600.58 4013.31,600.58 4018.63,605.9 4018.63,606.24 4020.98,608.59 4021.69,608.59 4023.62,610.52 U62.7@4023.62,620.37
NetR214_1: R214.1 U62.8 | length 158.8
  Bottom Copper w5: R214.1@3882.34,649.5 3900.66,649.5 3910.7,639.47 3910.7,622.35 3921.15,611.9 4006.44,611.9 4007.87,613.33 U62.8@4007.87,620.37
NetTP21_1: TP21.1 U62.6 | length 222.8
  Top Copper w4.02: TP21.1@3852.06,639.85 TP21.1@3852.21,640 3874.21,662 3935.39,662 3963.53,633.86 4023.26,633.86 v5(4039.56,617.56)
  Bottom Copper w4.02: v5(4039.56,617.56) 4040.5,617.56 U62.6@4045.27,622.33
NetTP25_1: TP25.1 U62.5 | length 53.4
  Bottom Copper w4.02: U62.5@4045.27,638.08 4065.95,638.08 TP25.1@4089.11,661.24
nRST_LED: D7.1 R56.2 | length 42.3
  Top Copper w4: D7.1@1717.63,682.09 R56.2@1717.63,724.41
PCIE_1V0: C36.2 C37.2 C42.2 C43.2 C44.2 C45.2 C46.2 C47.2 L2.2 U4.3 U4.8 U4.22 U4.30 | length 585.1
  Top Copper w5: U4.30@1658.76,1171.22 1658.76,1150.03 v3(1668.55,1140.24) ; U4.3@1708.96,1221.42 1709.51,1220.87 1746.91,1220.87 v3(1748.03,1219.75) ; U4.8@1708.96,1300.16 1714.97,1300.16 1716.3,1301.49 1716.3,1325.88 1728.35,1337.92 v3(1728.35,1338.58)
  Top Copper w7.87: C47.2@1401.1,1190.74 C47.2@1401.18,1190.66 ; v3(1401.57,1150.85) 1401.57,1190.27 C47.2@1401.18,1190.66 ; C36.2@1422.03,1011.37 1426.4,1015.74 C37.2@1426.4,1065.94 ; U4.22@1561.32,1221.42 1547.45,1221.42 1545.97,1219.93 1507.76,1219.93 1475.13,1187.29 1452.49,1187.29 C45.2@1449.12,1190.66 C47.2@1401.18,1190.66
  Bottom Copper w5: C44.2@1640.96,1169.33 1668.55,1141.73 v3(1668.55,1140.24) ; v3(1728.35,1338.58) 1728.35,1318.98 1723.52,1314.15 C46.2@1723.52,1267.39 C43.2@1723.52,1218.1 1725.17,1219.75 v3(1748.03,1219.75)
  other v3: 1368.41,1046 1354.33,1060.94 1381.89,1060.94
PCIe_CLKREQ_N_1V8: J3.65 U6.4 | length 1775.2
  Top Copper w4.02: v3(688.52,1099) 746.33,1099 855.99,1208.66 v3(1062.01,1208.66)
  Signal Layer 2 w4.02: v3(1062.01,1208.66) 1063.12,1207.55 1083,1207.55 1099.45,1224 1181.89,1224 1205.25,1200.65 1268.04,1200.65 v3(1341.25,1127.43)
  Bottom Copper w4.02: J3.65@-202.76,1295.28 528.72,1295.28 688.52,1135.48 v3(688.52,1099)
  Bottom Copper w6: v3(1341.25,1127.43) 1341.83,1126.85 1341.83,1092.69 U6.4@1342.4,1092.12
PCIe_CLKREQ_N_3V3: R46.2 U4.12 U6.1 | length 596
  Top Copper w5: v3(1642.72,1332.68) 1642.72,1319.16 U4.12@1643.01,1318.86
  Bottom Copper w5: U6.1@1401.46,1092.12 1401.46,1082.28 1407.36,1076.37 R46.2@1407.36,1042.91 1407.36,1019.64 1417,1010 1549,1010 1576.22,1037.22 1576.22,1262.22 1638.74,1324.74 1638.74,1325.73 1642.72,1329.7 v3(1642.72,1332.68)
PCIe_ISOLATE_N_1V8: R27.2 U6.5 | length 1929.4
  Top Copper w4.02: v3(655.51,1119.09) 749.09,1119.09 852.8,1222.8 v3(1076.15,1222.8)
  Signal Layer 2 w4.02: v3(1076.15,1222.8) 1086.25,1232.9 1185.1,1232.9 1209.34,1208.66 1311.53,1208.66 v3(1320.98,1218.1)
  Signal Layer 4 w4.02: v3(-384.91,1332) -383.84,1330.93 -383.84,1290.57 -343.27,1250 -209,1250 -70.22,1111.22 v3(-11.81,1111.22)
  Bottom Copper w4.02: v3(-11.81,1111.22) 636.81,1111.22 644.2,1118.61 655.02,1118.61 v3(655.51,1119.09)
  Bottom Copper w5: R27.2@-386,1311.72 -384.91,1312.81 v3(-384.91,1332) ; v3(1320.98,1218.1) 1338.99,1218.1 1342.4,1214.7 U6.5@1342.4,1214.17
PCIe_ISOLATE_N_3V3: R49.2 U4.20 U6.8 | length 225.7
  Top Copper w5: v3(1480.02,1244.86) 1512.82,1244.86 1518.31,1250.35 1548.14,1250.35 1550.7,1252.91 U4.20@1561.32,1252.91
  Bottom Copper w5: U6.8@1401.46,1214.17 1401.46,1258.19 R49.2@1409.45,1266.18 1409.45,1264.21 1426.78,1246.89 1472.98,1246.89 1477.04,1250.95 1477.04,1250.81 1480.02,1247.83 v3(1480.02,1244.86)
PCIe_PERST_1V8: J3.68 Q1.1 | length 573.1
  Signal Layer 4 w5: v2(-350.88,1311.02) -334,1327.9 -35.9,1327.9 93.47,1198.53 v6(94.53,1198.53)
  Bottom Copper w6: v2(-350.88,1311.02) J3.68@-324.02,1311.02 ; v6(94.53,1198.53) Q1.1@94.53,1238.74
PCIe_PERST_N_3V3: Q1.3 R28.2 U4.19 | length 1566.8
  Top Copper w4.02: v3(655.51,1139.76) 754.23,1139.76 851.46,1237 1129.01,1237 1214.84,1322.83 1406.03,1322.83 1470,1258.86 1543.36,1258.86 1549.55,1265.05 1549.55,1265.69 1552.52,1268.66 U4.19@1561.32,1268.66
  Bottom Copper w4.02: Q1.3@131.93,1159.99 131.93,1161.96 155,1185.04 224.99,1185.04 R28.2@226.42,1183.62 226.86,1184.06 611.22,1184.06 v3(655.51,1139.76)
PCIe_ROOT_PERST_1V8: J3.63 R79.2 | length 79.9
  Bottom Copper w5: J3.63@-202.76,1279.53 -161.96,1279.53 -155,1272.56 -155,1244.69 R79.2@-154,1243.69
PCIe_WAKE_N: R29.2 U4.21 | length 49.9
  Top Copper w5: v3(1539.37,1235.86) 1540.13,1236.62 1560.77,1236.62 U4.21@1561.32,1237.17
  Bottom Copper w5: R29.2@1515.75,1228.35 1524.07,1236.67 1524.89,1235.86 v3(1539.37,1235.86)
PG_LED: D3.1 R53.2 | length 46.3
  Top Copper w4: D3.1@1657.48,682.09 R53.2@1657.48,728.35
RCL: R10.2 U1.9 | length 101.7
  Top Copper w5.91: v3(3996.61,1145.67) 3995.09,1147.19 3995.09,1168.19 4008,1181.1 U1.9@4037.53,1181.1
  Bottom Copper w5.91: v3(3996.61,1145.67) 4021.78,1145.67 R10.2@4025.72,1141.73
RDET: R11.2 U1.6 | length 67.4
  Top Copper w5.91: v3(4008,1245.08) 4011.82,1245.08 4016.74,1240.16 U1.6@4037.53,1240.16
  Bottom Copper w5.91: v3(4008,1245.08) 4025.72,1227.36 R11.2@4025.72,1216.54
REGOUT: L2.1 U4.24
RXB_N: D10.4 D10.7 J8.B10 U61.18 | length 510.3
  Top Copper w5.12: v3(4137.89,778.43) 4143.59,772.72 4195.62,772.72 4199.41,776.51 4199.41,776.86 4200.79,778.23 D10.4@4207.97,778.23 4215.16,778.23 4216.54,776.86 4216.54,776.51 4219.53,773.51 4229.29,773.51 4232.28,776.51 4232.28,776.86 4233.66,778.23 D10.7@4240.85,778.23 4248.03,778.23 4249.41,776.86 4249.41,776.51 4252.41,773.51 4262.97,773.51 4286.92,797.46 4325.96,797.46 4349.8,773.62 4349.8,744.97 4356.92,737.86 4396.51,737.86 4409.84,724.53 4409.84,710.38 v2(4414.62,705.6)
  Bottom Copper w5.12: U61.18@4062.64,787.69 4069.53,787.69 4074.25,782.97 4093.35,782.97 4102.02,774.31 4133.77,774.31 v3(4137.89,778.43) ; J8.B10@4409.45,761.31 4409.45,758.71 4398.82,748.08 4398.82,741.25 4409.74,730.33 4409.74,710.48 v2(4414.62,705.6)
RXB_P: D10.5 D10.6 J8.B11 U61.19 | length 525.1
  Top Copper w5.12: v3(4137.98,758.44) 4142.03,762.49 4196.85,762.49 4199.85,759.49 4216.1,759.49 4216.54,759.93 4216.54,760.28 4219.53,763.27 4229.29,763.27 4232.28,760.28 4232.28,759.93 4233.66,758.55 D10.6@4240.85,758.55 4248.03,758.55 4249.41,759.93 4249.41,760.28 4252.41,763.27 4267.21,763.27 4291.16,787.23 4321.72,787.23 4339.57,769.38 4339.57,740.73 4352.68,727.63 4352.68,716.49 4355.67,713.49 4369.99,713.49 4373.12,716.62 4373.12,724.63 4376.12,727.63 4392.27,727.63 4399.61,720.29 4399.61,710.59 v2(4394.62,705.6)
  Bottom Copper w5.12: U61.19@4053.16,765.64 4067.17,765.64 4074.25,772.73 4089.11,772.73 4097.78,764.07 4132.36,764.07 v3(4137.98,758.44) ; J8.B11@4377.95,761.31 4377.95,758.71 4388.58,748.08 4388.58,737.01 4399.5,726.09 4399.5,710.48 v2(4394.62,705.6)
RXC_N: D9.5 D9.6 J8.A10 U61.14 | length 684.4
  Top Copper w5.12: v3(4183,871.57) 4188.84,877.42 4198.44,877.42 4201.84,874.02 D9.5@4209.02,874.02 4216.21,874.02 4217.59,875.39 4217.59,875.74 4220.58,878.74 4230.33,878.74 4233.33,875.74 4233.33,875.39 4234.71,874.02 D9.6@4241.9,874.02 4249.08,874.02 4250.46,875.39 4250.46,875.74 4253.46,878.74 4275.45,878.74 4310.1,913.39 4434.45,913.39 4457.88,913.39 cw(c4457.88,902.95) 4468.31,902.95 4468.31,893.61 ccw(c4478.74,893.61) 4478.74,883.18 ccw(c4478.74,893.61) 4489.18,893.61 4489.18,902.95 cw(c4499.61,902.95) 4499.61,913.39 4513.78,913.39 4534.25,913.39 4546.06,901.57 4546.06,860.53 4541.34,855.8 J8.A10@4541.34,838.08
  Bottom Copper w5.12: U61.14@4062.64,866.43 4069.53,866.43 4074.05,861.9 4163.16,861.9 4169.29,855.78 4199.36,855.78 4202.36,858.77 4202.36,874.25 4199.36,877.24 4188.67,877.24 v3(4183,871.57)
RXC_P: D9.4 D9.7 J8.A11 U61.15 | length 693.9
  Top Copper w5.12: v3(4183,891.56) 4186.91,887.65 4198.12,887.65 4200.46,889.99 4200.46,892.32 4201.84,893.7 D9.4@4209.02,893.7 4216.21,893.7 4217.59,892.32 4217.59,891.97 4220.58,888.98 4230.33,888.98 4233.33,891.97 4233.33,892.32 4234.71,893.7 D9.7@4241.9,893.7 4249.08,893.7 4250.46,892.32 4250.46,891.97 4253.46,888.98 4271.21,888.98 4305.86,923.62 4538.49,923.62 4556.3,905.81 4556.3,860.53 4561.02,855.8 J8.A11@4561.02,838.08
  Bottom Copper w5.12: U61.15@4062.64,846.75 4069.53,846.75 4074.45,851.67 4158.92,851.67 4165.05,845.54 4203.6,845.54 4212.6,854.53 4212.6,878.49 4203.6,887.48 4187.08,887.48 v3(4183,891.56)
sd_hst0_clk: J2.61 J7.5 | length 639.6
  Top Copper w4.02: J7.5@949.04,676.18 949.04,755.51 1003.03,809.5 1017.77,809.5 v3(1019.68,811.42) ; v3(1052.38,811.02) 1052.38,880.88 1192,1020.5 1192,1111.75 1222.56,1142.31 v3(1228.35,1142.31)
  Bottom Copper w4.02: v3@1019.88,811.22 v3@1052.19,811.22
  Bottom Copper w6: v3(1019.68,811.42) v3@1019.88,811.22 ; v3@1052.19,811.22 v3(1052.38,811.02) ; v3(1228.35,1142.31) 1231.05,1142.31 1233.87,1145.13 1252.41,1145.13 J2.61@1252.95,1145.67
sd_hst0_cmd: J2.63 J7.3 | length 591.1
  Top Copper w4.02: J7.3@1035.65,676.18 1035.65,881.65 1183.81,1029.81 1183.81,1117.88 1226.43,1160.51 v3(1228.35,1162.42)
  Bottom Copper w6: v3(1228.35,1162.42) 1228.85,1161.92 1252.45,1161.92 J2.63@1252.95,1161.42
sd_hst0_dat_0: J2.40 J7.7 | length 614.7
  Top Copper w6: v3(858.27,779.53) 858.27,776.82 862.2,772.88 862.2,676.4 J7.7@862.42,676.18
  Bottom Copper w4.02: v3(858.27,779.53) 858.38,779.64 870.19,779.64 872.33,781.77 873.75,783.19 ccw(c866.76,790.18) 873.75,797.17 864.86,806.06 cw(c871.84,813.05) 864.86,820.03 cw(c871.84,813.05) 878.83,820.03 889.93,808.94 ccw(c896.91,815.93) 903.9,808.94 ccw(c896.91,815.93) 903.9,822.91 892.81,834.01 cw(c899.79,841) 892.81,847.98 cw(c899.79,841) 906.78,847.98 917.88,836.89 ccw(c924.86,843.88) 931.85,836.89 ccw(c924.86,843.88) 931.85,850.86 920.76,861.96 cw(c927.74,868.95) 920.76,875.93 cw(c927.74,868.95) 934.73,875.93 943.62,867.04 ccw(c950.61,874.03) 957.6,867.04 971.27,880.72 1057.79,967.24 1117.4,967.24 1120.91,970.75 1120.91,971.9 1121.46,972.44 J2.40@1131.69,972.44
sd_hst0_dat_1: J2.38 J7.8 | length 600.7
  Top Copper w6: J7.8@821.09,676.18 822.83,677.93 822.83,713.83 826.77,717.77 v3(826.77,720.47)
  Bottom Copper w4.02: v3(826.77,720.47) 828.74,722.44 836.61,722.44 879.94,765.77 895.34,781.16 cw(c902.32,774.18) 909.31,781.16 926.12,764.36 ccw(c933.1,771.35) 940.09,764.36 ccw(c933.1,771.35) 940.09,778.33 919.35,799.08 cw(c926.34,806.06) 919.35,813.05 cw(c926.34,806.06) 933.32,813.05 954.07,792.31 ccw(c961.05,799.3) 968.04,792.31 ccw(c961.05,799.3) 968.04,806.28 951.24,823.09 cw(c958.22,830.08) 951.24,837.06 970.47,856.3 1070.87,956.69 J2.38@1131.69,956.69
sd_hst0_dat_2: J2.36 J7.1 | length 607.5
  Top Copper w5: J7.1@1122.27,676.18 1122.27,724.41 1122.27,726.91 ccw(c1111.89,726.91) 1111.89,737.28 1080.44,737.28 cw(c1080.44,747.66) 1080.44,758.03 1123.24,758.03 ccw(c1123.24,768.41) 1123.24,778.78 1080.44,778.78 cw(c1080.44,789.15) 1080.44,799.53 1123.24,799.53 ccw(c1123.24,809.9) 1123.24,820.28 1080.44,820.28 cw(c1080.44,830.65) 1080.44,841.02 1111.89,841.02 ccw(c1111.89,851.4) 1122.27,851.4 1122.27,880.93 1122.27,906.94 v3(1155.72,940.39)
  Bottom Copper w5: J2.36@1131.69,940.94 1131.97,940.67 1155.44,940.67 v3(1155.72,940.39)
sd_hst0_dat_3: J2.32 J7.2 | length 628.6
  Top Copper w5: v3(1078.74,705.71) 1078.74,676.4 J7.2@1078.96,676.18
  Bottom Copper w5: v3(1078.74,705.71) 1078.74,708.6 1078.74,711.1 ccw(c1068.37,711.1) 1068.37,721.48 1028.58,721.48 cw(c1028.58,731.85) 1028.58,742.23 1088.05,742.23 ccw(c1088.05,752.6) 1088.05,762.97 1028.58,762.97 cw(c1028.58,773.35) 1028.58,783.72 1068.37,783.72 ccw(c1068.37,794.1) 1078.74,794.1 1078.74,812.73 1078.74,832.14 1078.74,834.64 ccw(c1068.37,834.64) 1068.37,845.02 1021.2,845.02 cw(c1021.2,855.39) 1021.2,865.76 1065.21,865.76 ccw(c1065.21,876.14) 1072.54,868.8 1098.43,894.68 1113.19,909.45 J2.32@1131.69,909.45
SDS_RXD1_N: C51.2 U4.18 | length 53.1
  Top Copper w5.12: C51.2@1517.18,1295.24 1517.97,1295.24 1523.39,1300.65 1529.34,1300.65 1545.58,1284.41 U4.18@1561.32,1284.41
SDS_RXD1_P: C35.2 U4.17 | length 51.9
  Top Copper w5.12: C35.2@1517.18,1318.86 1517.97,1318.86 1523.39,1313.44 1534.64,1313.44 1547.92,1300.16 U4.17@1561.32,1300.16
SDS_RXD_N: C51.1 J3.77 | length 1910.7
  Top Copper w5.12: v3(727.57,1409.45) 727.57,1406.51 732.93,1401.15 732.93,1371.86 732.93,1321.47 787.19,1267.21 1100,1267.21 1198.93,1366.14 1420.06,1366.14 1441.33,1344.88 1441.33,1331.92 1472.59,1300.65 1488.93,1300.65 1494.35,1295.24 C51.1@1495.14,1295.24
  Bottom Copper w5.12: J3.77@-202.76,1389.76 -201.77,1388.78 -189.57,1388.78 -189.07,1388.28 729.93,1388.28 732.93,1391.28 732.93,1404.09 v3(727.57,1409.45)
SDS_RXD_P: C35.1 J3.75 | length 1907.8
  Top Copper w5.12: v3@751.07,1406.51 745.72,1401.15 745.72,1366.56 745.72,1326.77 792.49,1280 1094.7,1280 1193.63,1378.93 1425.36,1378.93 1454.12,1350.17 1454.12,1337.22 1477.89,1313.44 1488.93,1313.44 1494.35,1318.86 C35.1@1495.14,1318.86
  Bottom Copper w5.12: J3.75@-202.76,1374.02 -201.77,1375 -189.57,1375 -189.07,1375.49 735.23,1375.49 745.72,1385.99 745.72,1404.09 v3(751.07,1409.45)
SDS_TXD_N: J3.71 U4.14 | length 2006.5
  Top Copper w5.12: v2(796,1368.72) 799.63,1365.09 799.63,1348.17 812.84,1334.96 882.87,1334.96 919.29,1334.96 cw(c919.29,1324.52) 929.72,1324.52 929.72,1321.92 ccw(c940.16,1321.92) 940.16,1311.49 ccw(c940.16,1321.92) 950.59,1321.92 950.59,1324.52 cw(c961.02,1324.52) 961.02,1334.96 963.58,1334.96 1067.24,1334.96 1154.75,1422.47 1457.55,1422.47 v3(1461,1419.02) ; v3(1606.3,1354.33) 1606.3,1351.39 1611.71,1345.97 1611.71,1319.05 U4.14@1611.52,1318.86
  Signal Layer 2 w5.12: v3(1461,1419.02) 1463.03,1421.04 1560.16,1421.04 1610.29,1370.91 1610.29,1358.32 v3(1606.3,1354.33)
  Bottom Copper w5.12: J3.71@-202.76,1342.52 -201.77,1341.54 -189.57,1341.54 -189.07,1341.04 293.47,1341.04 793.95,1341.04 799.21,1346.3 v2@799.21,1365.51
